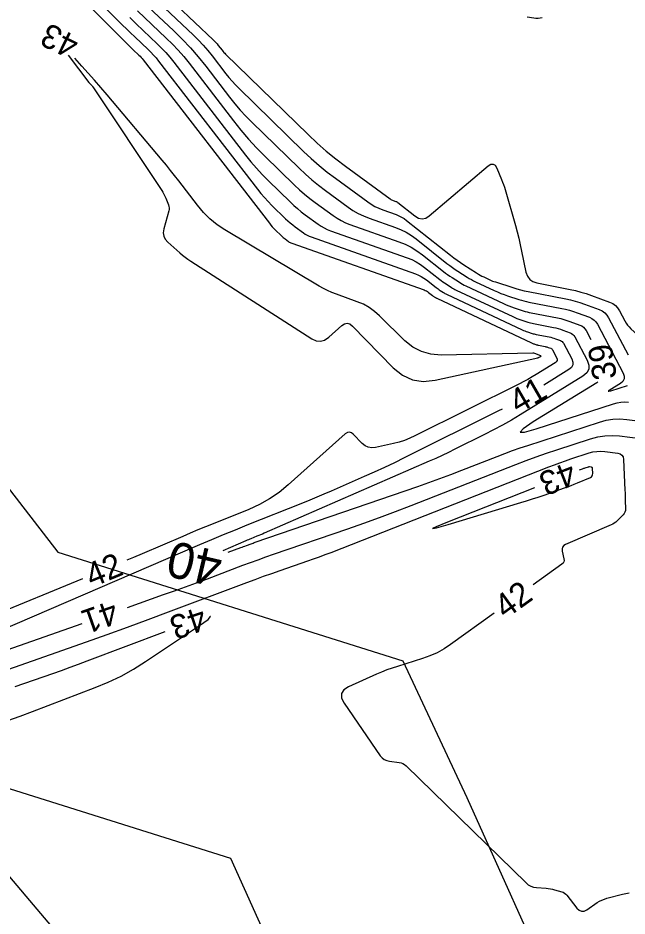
# Model space of a CAD drawing. Extents: x 2384780 to 2405861, y 547869 to 573706.
# Drawn here: x 2390047.8 to 2390098.5, y 552537.2 to 552612 of the extents above; entities that cross this region are included whole.
import ezdxf

# ---------------------------------------------------------------- set-up
doc = ezdxf.new("R2010")
doc.units = 0
for name, color, linetype in [('Old_Level_60', 7, 'Continuous'), ('Old_Level_61', 7, 'Continuous'), ('Prop Buffer Zone 1', 7, 'Continuous'), ('Prop Buffer Zone 2', 7, 'Continuous')]:
    doc.layers.add(name, color=color, linetype=linetype)

msp = doc.modelspace()

# ---------------------------------------------------------------- linework, layer by layer
at = {"layer": 'Old_Level_60'}
for points in [[(2390046.97025, 552620.938), (2390056.20525, 552611.71325), (2390056.53775, 552611.38325), (2390056.87225, 552611.0555), (2390057.20875, 552610.73), (2390057.5475, 552610.4065), (2390058.65725, 552609.3535), (2390058.89025, 552609.12375), (2390059.114, 552608.88525), (2390059.32825, 552608.6385), (2390059.53325, 552608.383), (2390067.7615, 552597.7145), (2390068.04475, 552597.36025), (2390068.34025, 552597.01675), (2390068.6475, 552596.68375), (2390068.9665, 552596.3615), (2390070.111, 552595.24575), (2390070.3005, 552595.0675), (2390070.496, 552594.89625), (2390070.6975, 552594.732), (2390070.90475, 552594.57475), (2390071.59175, 552594.07225), (2390071.742, 552593.9705), (2390071.8985, 552593.8805), (2390072.06125, 552593.80225), (2390072.23, 552593.7355), (2390080.929, 552590.66), (2390081.1715, 552590.563), (2390081.4035, 552590.447), (2390081.62475, 552590.31225), (2390081.83575, 552590.1585), (2390082.636, 552589.52325), (2390082.7165, 552589.46075), (2390082.79875, 552589.4005), (2390082.88225, 552589.34225), (2390082.9675, 552589.286), (2390083.248, 552589.106), (2390083.3085, 552589.06825), (2390083.37025, 552589.03275), (2390083.43325, 552588.99925), (2390083.49725, 552588.96775), (2390089.791, 552586.00625), (2390089.90225, 552585.956), (2390090.01525, 552585.90925), (2390090.1295, 552585.86625), (2390090.24525, 552585.827), (2390090.6255, 552585.7045), (2390090.70725, 552585.6795), (2390090.78975, 552585.65675), (2390090.873, 552585.63675), (2390090.9565, 552585.619), (2390092.05775, 552585.4035), (2390092.189, 552585.375), (2390092.3185, 552585.3415), (2390092.44675, 552585.30275), (2390092.57375, 552585.259), (2390092.9855, 552585.107), (2390093.06825, 552585.06825), (2390093.13975, 552585.01675), (2390093.20025, 552584.9525), (2390093.24975, 552584.87575)], [(2390047.901, 552618.83125), (2390056.865, 552609.877), (2390057.00475, 552609.73825), (2390057.1455, 552609.6005), (2390057.287, 552609.4635), (2390057.4295, 552609.3275), (2390057.89625, 552608.8845), (2390057.9945, 552608.78775), (2390058.0885, 552608.6875), (2390058.17875, 552608.58375), (2390058.26475, 552608.47625), (2390068.756, 552594.874), (2390068.87425, 552594.726), (2390068.9975, 552594.58275), (2390069.1255, 552594.44375), (2390069.25875, 552594.30925), (2390069.73625, 552593.84375), (2390069.8155, 552593.7695), (2390069.897, 552593.698), (2390069.981, 552593.6295), (2390070.0675, 552593.56375), (2390070.354, 552593.35425), (2390070.41675, 552593.31175), (2390070.48225, 552593.27425), (2390070.55, 552593.2415), (2390070.6205, 552593.21375), (2390081.6295, 552589.3215), (2390081.72925, 552589.2815), (2390081.825, 552589.23375), (2390081.91625, 552589.17825), (2390082.00325, 552589.11475), (2390082.33325, 552588.85275), (2390082.36675, 552588.827), (2390082.4005, 552588.802), (2390082.435, 552588.778), (2390082.47, 552588.755), (2390082.58575, 552588.6805), (2390082.61075, 552588.665), (2390082.63625, 552588.6505), (2390082.66225, 552588.6365), (2390082.68875, 552588.6235), (2390090.56875, 552584.91525), (2390090.625, 552584.89), (2390090.682, 552584.8665), (2390090.7395, 552584.84475), (2390090.798, 552584.825), (2390090.98975, 552584.76325), (2390091.031, 552584.7505), (2390091.0725, 552584.73925), (2390091.1145, 552584.729), (2390091.1565, 552584.72025), (2390091.71175, 552584.6115), (2390091.778, 552584.59725), (2390091.84325, 552584.58025), (2390091.908, 552584.56075), (2390091.972, 552584.5385), (2390092.1795, 552584.462), (2390092.22125, 552584.4425), (2390092.2575, 552584.4165), (2390092.288, 552584.384), (2390092.31275, 552584.34525), (2390092.65825, 552583.69075), (2390092.70625, 552583.5575), (2390092.70175, 552583.43875), (2390092.645, 552583.334), (2390092.53625, 552583.24375), (2390090.964, 552582.2765), (2390090.625, 552582.073), (2390090.28175, 552581.87725), (2390089.93425, 552581.68925), (2390089.5825, 552581.50875), (2390080.87375, 552577.16425), (2390080.4455, 552576.96675), (2390080.008, 552576.797), (2390079.5605, 552576.65475), (2390079.10325, 552576.54025), (2390077.58725, 552576.209), (2390077.27875, 552576.17725), (2390076.99275, 552576.2215), (2390076.73, 552576.34175), (2390076.48975, 552576.538), (2390075.74275, 552577.304), (2390075.58125, 552577.4285), (2390075.417, 552577.47375), (2390075.25025, 552577.43975), (2390075.0805, 552577.3265), (2390070.32875, 552573.07825), (2390069.57575, 552572.461), (2390068.77775, 552571.91625), (2390067.93525, 552571.44325), (2390067.048, 552571.04275), (2390064.076, 552569.852), (2390063.44, 552569.595), (2390062.8055, 552569.33375), (2390062.17275, 552569.069), (2390061.54175, 552568.8), (2390058.1625, 552567.34825), (2390057.438, 552567.0385), (2390056.88475, 552566.8045)], [(2390056.45225, 552617.4005), (2390064.08475, 552610.15825), (2390064.1975, 552610.047), (2390064.30575, 552609.93175), (2390064.40925, 552609.8125), (2390064.5085, 552609.689), (2390064.82475, 552609.279), (2390064.894, 552609.19225), (2390064.966, 552609.10825), (2390065.04125, 552609.027), (2390065.11925, 552608.94825), (2390071.98475, 552602.25575), (2390072.7265, 552601.558), (2390073.4915, 552600.8875), (2390074.27975, 552600.2445), (2390075.091, 552599.629), (2390078.8175, 552596.90425), (2390078.876, 552596.86475), (2390078.93675, 552596.82975), (2390079, 552596.79925), (2390079.06575, 552596.77325), (2390079.28425, 552596.696), (2390079.33, 552596.67775), (2390079.37375, 552596.65575), (2390079.41575, 552596.63025), (2390079.4555, 552596.60125), (2390080.86875, 552595.4795), (2390081.1705, 552595.30025), (2390081.4705, 552595.24375), (2390081.76875, 552595.30975), (2390082.06475, 552595.498), (2390086.9675, 552599.64425), (2390087.1945, 552599.78675), (2390087.39125, 552599.805), (2390087.558, 552599.69875), (2390087.69425, 552599.468), (2390088.09075, 552598.5115), (2390088.1725, 552598.3055), (2390088.2485, 552598.09725), (2390088.31825, 552597.887), (2390088.38175, 552597.67475), (2390089.23275, 552594.6775), (2390089.37775, 552594.14975), (2390089.513, 552593.6195), (2390089.639, 552593.087), (2390089.7555, 552592.552), (2390090.12025, 552590.801), (2390090.23575, 552590.4635), (2390090.42575, 552590.2015), (2390090.69, 552590.01475), (2390091.029, 552589.9035), (2390093.7875, 552589.3635), (2390094.24375, 552589.26475), (2390094.695, 552589.148), (2390095.141, 552589.01325), (2390095.58225, 552588.8605), (2390097.07725, 552588.3095), (2390097.33575, 552588.188), (2390097.5595, 552588.027), (2390097.74875, 552587.8265), (2390097.90325, 552587.58625)], [(2390056.191, 552616.45725), (2390062.43975, 552610.528), (2390062.85075, 552610.12275), (2390063.24525, 552609.7025), (2390063.623, 552609.26725), (2390063.98425, 552608.81725), (2390065.13725, 552607.32225), (2390065.38975, 552607.00675), (2390065.65275, 552606.7005), (2390065.9265, 552606.404), (2390066.21075, 552606.11675), (2390071.61, 552600.85375), (2390072.24125, 552600.25975), (2390072.8925, 552599.68925), (2390073.56325, 552599.142), (2390074.25375, 552598.618), (2390076.94125, 552596.65325), (2390077.23825, 552596.452), (2390077.54725, 552596.27425), (2390077.8685, 552596.1195), (2390078.202, 552595.98775), (2390079.3115, 552595.5955), (2390079.54425, 552595.50225), (2390079.767, 552595.391), (2390079.9795, 552595.2615), (2390080.182, 552595.11375), (2390083.846, 552592.2055), (2390084.11625, 552591.9965), (2390084.3915, 552591.79425), (2390084.6715, 552591.599), (2390084.95675, 552591.41075), (2390086.00875, 552590.735), (2390086.15525, 552590.644), (2390086.3045, 552590.55825), (2390086.4565, 552590.4775), (2390086.61125, 552590.4015), (2390087.12125, 552590.1615), (2390087.23125, 552590.112), (2390087.3425, 552590.06575), (2390087.45525, 552590.0235), (2390087.5695, 552589.9845), (2390089.0295, 552589.51425), (2390089.3435, 552589.418), (2390089.66, 552589.3315), (2390089.979, 552589.25425), (2390090.30025, 552589.18625), (2390093.4415, 552588.5715), (2390093.83275, 552588.48675), (2390094.21975, 552588.38675), (2390094.60225, 552588.271), (2390094.9805, 552588.14025), (2390096.209, 552587.6875), (2390096.45575, 552587.5715), (2390096.6695, 552587.41775), (2390096.85, 552587.22625), (2390096.9975, 552586.997), (2390098.62775, 552583.907)], [(2390057.01325, 552614.48625), (2390060.795, 552610.898), (2390061.50425, 552610.1985), (2390062.18475, 552609.47325), (2390062.83675, 552608.72225), (2390063.46025, 552607.9455), (2390065.45, 552605.36575), (2390065.8855, 552604.821), (2390066.3395, 552604.29275), (2390066.81175, 552603.781), (2390067.3025, 552603.2855), (2390071.23525, 552599.45175), (2390071.75625, 552598.96175), (2390072.29325, 552598.491), (2390072.84675, 552598.0395), (2390073.4165, 552597.60725), (2390075.3045, 552596.22675), (2390075.7175, 552595.947), (2390076.14775, 552595.6995), (2390076.59475, 552595.48425), (2390077.05875, 552595.301), (2390079.255, 552594.5245), (2390079.71575, 552594.34025), (2390080.1565, 552594.11975), (2390080.5775, 552593.8635), (2390080.9785, 552593.571), (2390083.5435, 552591.535), (2390083.76625, 552591.3625), (2390083.99325, 552591.19575), (2390084.22425, 552591.03475), (2390084.4595, 552590.8795), (2390085.23425, 552590.38175), (2390085.40175, 552590.278), (2390085.5725, 552590.17975), (2390085.7465, 552590.08725), (2390085.9235, 552590.0005), (2390087.45725, 552589.2785), (2390087.73425, 552589.1535), (2390088.015, 552589.0375), (2390088.29925, 552588.93075), (2390088.587, 552588.833), (2390089.533, 552588.528), (2390089.73675, 552588.46575), (2390089.94175, 552588.40975), (2390090.14825, 552588.3595), (2390090.3565, 552588.3155), (2390093.0955, 552587.7795), (2390093.42175, 552587.70875), (2390093.7445, 552587.62525), (2390094.06325, 552587.529), (2390094.37875, 552587.42), (2390095.40325, 552587.04225), (2390095.60875, 552586.94575), (2390095.787, 552586.8175), (2390095.9375, 552586.658), (2390096.0605, 552586.46675), (2390098.212, 552582.38925), (2390098.3035, 552582.13475), (2390098.295, 552581.9075), (2390098.18675, 552581.70775), (2390097.9785, 552581.53525), (2390097.13525, 552581.01625), (2390097.00225, 552580.92725), (2390096.965, 552580.88225), (2390097.02325, 552580.88175), (2390097.17725, 552580.92525), (2390098.559, 552581.3755)], [(2390057.78325, 552612.56475), (2390060.17875, 552610.2915), (2390060.682, 552609.79525), (2390061.165, 552609.28075), (2390061.62775, 552608.74775), (2390062.07, 552608.1965), (2390065.77275, 552603.396), (2390066.38625, 552602.62875), (2390067.0255, 552601.88475), (2390067.691, 552601.1635), (2390068.38225, 552600.46575), (2390070.8605, 552598.04975), (2390071.271, 552597.66375), (2390071.69425, 552597.29275), (2390072.13025, 552596.937), (2390072.57925, 552596.59625), (2390074.067, 552595.50875), (2390074.3925, 552595.28825), (2390074.73125, 552595.09325), (2390075.0835, 552594.9235), (2390075.44925, 552594.77925), (2390079.5285, 552593.337), (2390080.05575, 552593.126), (2390080.56025, 552592.87375), (2390081.04175, 552592.5805), (2390081.5005, 552592.24575), (2390083.241, 552590.8645), (2390083.4165, 552590.72875), (2390083.595, 552590.5975), (2390083.777, 552590.47075), (2390083.962, 552590.3485), (2390084.572, 552589.9565), (2390084.704, 552589.87475), (2390084.8385, 552589.7975), (2390084.97525, 552589.7245), (2390085.11475, 552589.65625), (2390088.23525, 552588.18775), (2390088.457, 552588.08775), (2390088.68175, 552587.99475), (2390088.90925, 552587.90925), (2390089.13975, 552587.831), (2390089.89725, 552587.58675), (2390090.06025, 552587.537), (2390090.2245, 552587.492), (2390090.39, 552587.452), (2390090.5565, 552587.41675), (2390092.74975, 552586.9875), (2390093.01075, 552586.931), (2390093.269, 552586.864), (2390093.5245, 552586.787), (2390093.777, 552586.6995), (2390094.59725, 552586.39725), (2390094.762, 552586.32), (2390094.9045, 552586.21725), (2390095.02525, 552586.0895), (2390095.1235, 552585.9365), (2390095.52075, 552585.184)], [(2390091.46425, 552611.9865), (2390091.2935, 552611.9525), (2390091.122, 552611.936), (2390090.9495, 552611.93625), (2390090.77625, 552611.954), (2390090.20925, 552612.03975)], [(2390052.019, 552608.8775), (2390053.731, 552606.606), (2390053.75275, 552606.578), (2390053.775, 552606.551), (2390053.7985, 552606.52475), (2390053.8225, 552606.49925)], [(2390062.761, 552596.3775), (2390061.20775, 552598.413), (2390060.87225, 552598.84725), (2390060.53175, 552599.27725), (2390060.18625, 552599.70325), (2390059.83525, 552600.125), (2390055.249, 552605.5725), (2390054.73375, 552606.178), (2390054.2125, 552606.77825), (2390053.68475, 552607.37325), (2390053.151, 552607.9625), (2390052.553, 552608.616)], [(2390053.8225, 552606.49925), (2390053.93725, 552606.38125), (2390053.97125, 552606.3445), (2390054.00375, 552606.30625), (2390054.03425, 552606.2665), (2390054.063, 552606.2255), (2390059.7955, 552597.6095), (2390059.89325, 552597.45375), (2390059.98275, 552597.29325), (2390060.06325, 552597.1285), (2390060.1355, 552596.95925), (2390060.35725, 552596.399), (2390060.3945, 552596.2785), (2390060.41125, 552596.15675), (2390060.40775, 552596.03375), (2390060.38375, 552595.91), (2390059.969, 552594.398), (2390059.92275, 552594.0865), (2390059.96125, 552593.80025), (2390060.08475, 552593.53925), (2390060.2935, 552593.3035), (2390061.29925, 552592.4095), (2390061.518, 552592.22225), (2390061.74375, 552592.04425), (2390061.97625, 552591.87525), (2390062.21575, 552591.715), (2390072.2815, 552585.2635), (2390072.652, 552585.09), (2390073.0115, 552585.051), (2390073.3605, 552585.14675), (2390073.6985, 552585.37675), (2390074.78575, 552586.34875), (2390075.01675, 552586.503), (2390075.24425, 552586.54925), (2390075.468, 552586.4875), (2390075.688, 552586.318), (2390079.07225, 552582.84875), (2390079.83375, 552582.226), (2390080.6675, 552581.8445), (2390081.5735, 552581.70425), (2390082.552, 552581.80525), (2390091.11425, 552583.67575), (2390091.14225, 552583.6825), (2390091.1695, 552583.69125), (2390091.196, 552583.7015), (2390091.222, 552583.7135), (2390091.32875, 552583.767), (2390091.3355, 552583.77025), (2390091.342, 552583.77375), (2390091.3485, 552583.7775), (2390091.35475, 552583.78125), (2390091.37925, 552583.79625), (2390091.38125, 552583.798), (2390091.38225, 552583.8), (2390091.38225, 552583.802), (2390091.3815, 552583.8045), (2390091.37625, 552583.8145), (2390091.37575, 552583.81525), (2390091.375, 552583.816), (2390091.374, 552583.81675), (2390091.373, 552583.81725), (2390091.3695, 552583.8185), (2390091.36875, 552583.81875), (2390091.368, 552583.819), (2390091.36725, 552583.81925), (2390091.3665, 552583.81925), (2390091.35725, 552583.82125), (2390091.35625, 552583.82125), (2390091.35525, 552583.8215), (2390091.35425, 552583.822), (2390091.35325, 552583.82225), (2390091.35, 552583.82325), (2390091.34925, 552583.8235), (2390091.34875, 552583.82375), (2390091.348, 552583.824), (2390091.34725, 552583.82425), (2390091.00725, 552583.98425), (2390090.93325, 552584.01425), (2390090.8575, 552584.035), (2390090.78, 552584.047), (2390090.70025, 552584.04975), (2390083.0515, 552583.90075), (2390082.2065, 552583.9625), (2390081.424, 552584.182), (2390080.70425, 552584.55925), (2390080.047, 552585.094), (2390077.931, 552587.16875), (2390077.51275, 552587.538), (2390077.06225, 552587.85625), (2390076.58, 552588.12375), (2390076.06575, 552588.3405), (2390074.33375, 552588.965), (2390073.96675, 552589.10725), (2390073.60775, 552589.26675), (2390073.25675, 552589.4435), (2390072.914, 552589.637), (2390065.058, 552594.3275), (2390064.40975, 552594.757), (2390063.81075, 552595.24175), (2390063.26125, 552595.782), (2390062.761, 552596.3775)], [(2390097.90325, 552587.58625), (2390098.3515, 552586.73675), (2390098.45425, 552586.56), (2390098.57075, 552586.3935), (2390098.701, 552586.2375), (2390098.8445, 552586.092), (2390099.4025, 552585.57175), (2390099.518, 552585.457), (2390099.62575, 552585.3355), (2390099.7255, 552585.20775), (2390099.81775, 552585.07325), (2390100.7935, 552583.548), (2390100.9895, 552583.28825), (2390101.21875, 552583.06975), (2390101.48125, 552582.8925), (2390101.777, 552582.75675), (2390102.797, 552582.38025), (2390103.00325, 552582.2845), (2390103.18425, 552582.15875), (2390103.22725, 552582.11625)], [(2390093.24975, 552584.87575), (2390093.93475, 552583.57725), (2390094.02975, 552583.31325), (2390094.021, 552583.0775), (2390093.90875, 552582.87), (2390093.6925, 552582.691), (2390091.60125, 552581.40425)], [(2390096.10575, 552581.66875), (2390096.0055, 552581.5855), (2390090.70925, 552578.32675), (2390089.8745, 552577.76725), (2390089.6405, 552577.48575), (2390090.00675, 552577.48175), (2390090.9735, 552577.75575), (2390097.39425, 552579.8475), (2390097.7065, 552579.931), (2390098.022, 552579.97925), (2390098.341, 552579.992), (2390098.66325, 552579.9695)], [(2390088.138, 552579.4055), (2390087.8345, 552579.25), (2390079.9885, 552575.33575), (2390079.16225, 552574.93025), (2390078.33075, 552574.535), (2390077.4945, 552574.15075), (2390076.653, 552573.777), (2390073.8965, 552572.5735), (2390073.305, 552572.318), (2390072.71125, 552572.06675), (2390072.116, 552571.82025), (2390071.5185, 552571.57825), (2390066.89125, 552569.72425), (2390065.901, 552569.324), (2390064.91325, 552568.9175), (2390063.928, 552568.505), (2390062.94525, 552568.0865), (2390046.32475, 552560.94525)], [(2390056.946, 552562.88625), (2390059.95575, 552563.9465), (2390060.86875, 552564.27075), (2390061.78, 552564.6), (2390062.68975, 552564.93425), (2390063.5975, 552565.273), (2390066.56025, 552566.388), (2390067.19575, 552566.6245), (2390067.83325, 552566.8565), (2390068.47225, 552567.08375), (2390069.113, 552567.30625), (2390075.29825, 552569.42925), (2390076.621, 552569.89125), (2390077.93825, 552570.368), (2390079.2505, 552570.859), (2390080.55725, 552571.3645), (2390089.28025, 552574.79375), (2390090.1225, 552575.11775), (2390090.969, 552575.42875), (2390091.82025, 552575.7275), (2390092.676, 552576.01325), (2390095.50075, 552576.9335), (2390096.0935, 552577.092), (2390096.693, 552577.1835), (2390097.29875, 552577.20775), (2390097.911, 552577.165), (2390100.479, 552576.84625)], [(2390044.52875, 552556.84975), (2390053.54325, 552560.02525), (2390055.25025, 552560.63175), (2390056.95425, 552561.247), (2390058.65475, 552561.87175), (2390060.35175, 552562.50525), (2390066.87825, 552564.96125), (2390067.57225, 552565.21975), (2390068.26825, 552565.47275), (2390068.966, 552565.721), (2390069.6655, 552565.964), (2390071.95375, 552566.74925), (2390072.443, 552566.92025), (2390072.9305, 552567.0965), (2390073.416, 552567.27825), (2390073.8995, 552567.46525), (2390092.03375, 552574.59475), (2390092.4865, 552574.76875), (2390092.94175, 552574.936), (2390093.3995, 552575.0965), (2390093.8595, 552575.25025), (2390095.37825, 552575.745), (2390095.697, 552575.83025), (2390096.01925, 552575.8795), (2390096.345, 552575.8925), (2390096.67425, 552575.8695), (2390097.75525, 552575.73525), (2390097.95925, 552575.681), (2390098.108, 552575.57575), (2390098.2015, 552575.419), (2390098.23975, 552575.2115), (2390098.357, 552572.6445), (2390098.36625, 552572.431), (2390098.374, 552572.21775), (2390098.38075, 552572.00425), (2390098.386, 552571.791), (2390098.40175, 552571.0935), (2390098.3915, 552570.94975), (2390098.3535, 552570.817), (2390098.28825, 552570.6955), (2390098.1955, 552570.585), (2390097.69575, 552570.09325), (2390097.58475, 552569.99375), (2390097.466, 552569.9055), (2390097.33975, 552569.82875), (2390097.20575, 552569.7635), (2390093.417, 552568.12675), (2390093.25975, 552568.03175), (2390093.16025, 552567.9075), (2390093.11775, 552567.754), (2390093.13275, 552567.571), (2390093.27575, 552566.92525), (2390093.28825, 552566.79375), (2390093.26425, 552566.67625), (2390093.204, 552566.5725), (2390093.10725, 552566.48275), (2390090.7195, 552564.75875)], [(2390083.65275, 552569.784), (2390089.6855, 552571.60925), (2390090.17275, 552571.7595), (2390090.6585, 552571.915), (2390091.1425, 552572.0755), (2390091.625, 552572.241), (2390093.31325, 552572.8305), (2390093.59175, 552572.93025), (2390093.86875, 552573.035), (2390094.14375, 552573.144), (2390094.417, 552573.258), (2390095.48175, 552573.712), (2390095.57125, 552573.7645), (2390095.634, 552573.834), (2390095.6695, 552573.9205), (2390095.678, 552574.02425), (2390095.65825, 552574.454), (2390095.6505, 552574.4955), (2390095.632, 552574.52675), (2390095.602, 552574.548), (2390095.56125, 552574.55875), (2390095.40975, 552574.5775), (2390095.3775, 552574.57975), (2390095.3455, 552574.5785), (2390095.314, 552574.57375), (2390095.2825, 552574.5655), (2390095.0245, 552574.48125), (2390094.96925, 552574.46275), (2390094.91425, 552574.4435), (2390094.85975, 552574.4235), (2390094.8055, 552574.40275), (2390094.5585, 552574.3055)], [(2390090.836, 552572.842), (2390083.58125, 552569.99), (2390082.643, 552569.6065), (2390082.342, 552569.44425), (2390082.67875, 552569.5035), (2390083.65275, 552569.784)], [(2390053.189, 552565.2745), (2390037.81475, 552558.94525)], [(2390046.98525, 552553.4525), (2390048.01375, 552553.837), (2390049.041, 552554.22525), (2390054.2435, 552556.20225), (2390055.34275, 552556.65575), (2390056.4115, 552557.16875), (2390057.4495, 552557.7415), (2390058.45675, 552558.374), (2390062.95275, 552561.37625), (2390063.66025, 552561.88825), (2390063.856, 552562.13725), (2390063.831, 552562.13625)], [(2390087.4765, 552562.417), (2390083.847, 552559.7965), (2390083.295, 552559.4305), (2390082.719, 552559.11275), (2390082.119, 552558.843), (2390081.495, 552558.6215), (2390079.41725, 552557.97575), (2390078.9745, 552557.83075), (2390078.53675, 552557.6725), (2390078.10425, 552557.501), (2390077.6765, 552557.31625), (2390075.34825, 552556.2675), (2390074.9505, 552556.01475), (2390074.75525, 552555.70525), (2390074.76225, 552555.3395), (2390074.9715, 552554.917), (2390077.9925, 552550.5335), (2390078.14475, 552550.353), (2390078.32325, 552550.21575), (2390078.52775, 552550.12175), (2390078.7585, 552550.07075), (2390079.5545, 552549.9755), (2390079.719, 552549.9425), (2390079.87175, 552549.88475), (2390080.0125, 552549.802), (2390080.1415, 552549.69425), (2390090.122, 552539.9455), (2390090.31075, 552539.78925), (2390090.5175, 552539.67275), (2390090.74175, 552539.59575), (2390090.984, 552539.558), (2390091.804, 552539.5), (2390091.97875, 552539.48275), (2390092.152, 552539.45675), (2390092.32375, 552539.4215), (2390092.49375, 552539.377), (2390093.09625, 552539.20275), (2390093.2195, 552539.157), (2390093.331, 552539.09375), (2390093.431, 552539.0135), (2390093.5195, 552538.91625), (2390094.3555, 552537.843), (2390094.54225, 552537.6625), (2390094.7445, 552537.58025), (2390094.962, 552537.597), (2390095.195, 552537.712), (2390096.055, 552538.2995), (2390096.24325, 552538.4165), (2390096.43925, 552538.51625), (2390096.6435, 552538.5985), (2390096.8555, 552538.66325), (2390098.15475, 552539.00025), (2390098.43425, 552539.06475), (2390098.71625, 552539.11425)], [(2390041.697, 552557.5145), (2390053.17325, 552561.55725)], [(2390060.058, 552560.84825), (2390053.5665, 552558.40525), (2390052.8515, 552558.1385), (2390052.135, 552557.87525), (2390051.41725, 552557.616), (2390050.698, 552557.3605), (2390047.57625, 552556.26075)], [(2390045.25325, 552542.6145), (2390051.23925, 552535.585)]]:
    msp.add_lwpolyline(points, dxfattribs=at)
at = {"layer": 'Old_Level_61'}
for points in [[(2390057.1305, 552611.9965), (2390057.66525, 552611.4855), (2390059.418, 552609.8225), (2390059.78625, 552609.4595), (2390060.1395, 552609.083), (2390060.478, 552608.69325), (2390060.8015, 552608.28975), (2390066.767, 552600.55525), (2390067.2155, 552599.9945), (2390067.683, 552599.45075), (2390068.16925, 552598.92375), (2390068.6745, 552598.4135), (2390070.48575, 552596.64775), (2390070.78575, 552596.3655), (2390071.095, 552596.0945), (2390071.414, 552595.8345), (2390071.742, 552595.5855), (2390072.82925, 552594.7905), (2390073.06725, 552594.6295), (2390073.315, 552594.48675), (2390073.57225, 552594.36275), (2390073.8395, 552594.25725), (2390080.22875, 552591.9985), (2390080.6135, 552591.8445), (2390080.98175, 552591.6605), (2390081.33325, 552591.44625), (2390081.66825, 552591.20225), (2390082.9385, 552590.19375), (2390083.0665, 552590.09475), (2390083.197, 552589.999), (2390083.32975, 552589.9065), (2390083.46475, 552589.81725), (2390083.91, 552589.53125), (2390084.00625, 552589.4715), (2390084.1045, 552589.415), (2390084.20425, 552589.362), (2390084.306, 552589.312), (2390089.013, 552587.097), (2390089.17975, 552587.02175), (2390089.3485, 552586.952), (2390089.5195, 552586.88775), (2390089.6925, 552586.829), (2390090.2615, 552586.64575), (2390090.38375, 552586.60825), (2390090.507, 552586.5745), (2390090.6315, 552586.54425), (2390090.7565, 552586.518), (2390092.40375, 552586.1955), (2390092.6, 552586.153), (2390092.79375, 552586.10275), (2390092.98575, 552586.04475), (2390093.17525, 552585.97925), (2390093.79125, 552585.75225), (2390093.915, 552585.694), (2390094.02225, 552585.617), (2390094.11275, 552585.521), (2390094.18675, 552585.406), (2390095.2115, 552583.46375), (2390095.3535, 552583.069), (2390095.3405, 552582.71625), (2390095.17225, 552582.406), (2390094.849, 552582.13825), (2390089.62625, 552578.92475), (2390088.902, 552578.49), (2390088.1685, 552578.07175), (2390087.42575, 552577.66975), (2390086.674, 552577.28425), (2390084.2035, 552576.05175), (2390083.6725, 552575.791), (2390083.13825, 552575.53725), (2390082.601, 552575.29025), (2390082.06025, 552575.05025), (2390068.334, 552569.0575), (2390068.183, 552568.99225), (2390068.0315, 552568.928), (2390067.8795, 552568.86525), (2390067.727, 552568.8035), (2390067.228, 552568.6035), (2390067.12125, 552568.56025), (2390067.01475, 552568.5165), (2390066.9085, 552568.472), (2390066.8025, 552568.42675), (2390064.87775, 552567.6)], [(2390065.3165, 552567.49725), (2390066.36825, 552567.86775), (2390066.48725, 552567.91), (2390066.606, 552567.953), (2390066.72475, 552567.99675), (2390066.84325, 552568.04075), (2390067.2295, 552568.18625), (2390067.3125, 552568.217), (2390067.39575, 552568.24725), (2390067.479, 552568.277), (2390067.5625, 552568.306), (2390081.12825, 552572.96225), (2390082.044, 552573.282), (2390082.95625, 552573.612), (2390083.8645, 552573.952), (2390084.7695, 552574.302), (2390087.719, 552575.46175), (2390088.35275, 552575.7055), (2390088.99, 552575.9395), (2390089.6305, 552576.16425), (2390090.2745, 552576.3795), (2390096.22975, 552578.3195), (2390096.79175, 552578.46975), (2390097.35975, 552578.5565), (2390097.934, 552578.5795), (2390098.5145, 552578.539), (2390100.98525, 552578.23225)]]:
    msp.add_lwpolyline(points, dxfattribs=at)
at = {"layer": 'Prop Buffer Zone 1'}
for points in [[(2390005.01475, 552615.02175), (2390023.78025, 552599.87925), (2390034.69825, 552588.785), (2390051.1385, 552567.4905), (2390079.876, 552558.44225)], [(2390079.876, 552558.44225), (2390085.18275, 552547.05975), (2390092.88653, 552529.94684)]]:
    msp.add_lwpolyline(points, dxfattribs=at)
at = {"layer": 'Prop Buffer Zone 2'}
for points in [[(2389991.166, 552600.4975), (2390010.329, 552585.03425), (2390019.601, 552575.6125), (2390039.144, 552550.29925), (2390065.53175, 552541.99075)], [(2390065.53175, 552541.99075), (2390070.07489, 552531.89857)]]:
    msp.add_lwpolyline(points, dxfattribs=at)

# ---------------------------------------------------------------- texts
at = {"layer": 'Old_Level_60'}
for s, rotation, p in [('43', 153.8902889, (2390053.0605, 552610.28975)), ('39', 99.4519583, (2390097.7015, 552582.01025)), ('41', 29.9888, (2390089.46575, 552578.96275)), ('43', 201.4618889, (2390093.80425, 552575.0835)), ('42', 22.4879333, (2390053.9735, 552564.51275)), ('42', 35.8305139, (2390088.4135, 552561.86025)), ('41', 199.4055944, (2390055.737, 552563.5205)), ('43', 198.8458056, (2390063.1045, 552563.01025))]:
    msp.add_text(s, height=2, rotation=rotation, dxfattribs=at).set_placement(p)
at = {"layer": 'Old_Level_61'}
msp.add_text('40', height=3, rotation=166.8327611, dxfattribs=at).set_placement((2390065.03375, 552567.4525))

doc.saveas('drawing.dxf')
